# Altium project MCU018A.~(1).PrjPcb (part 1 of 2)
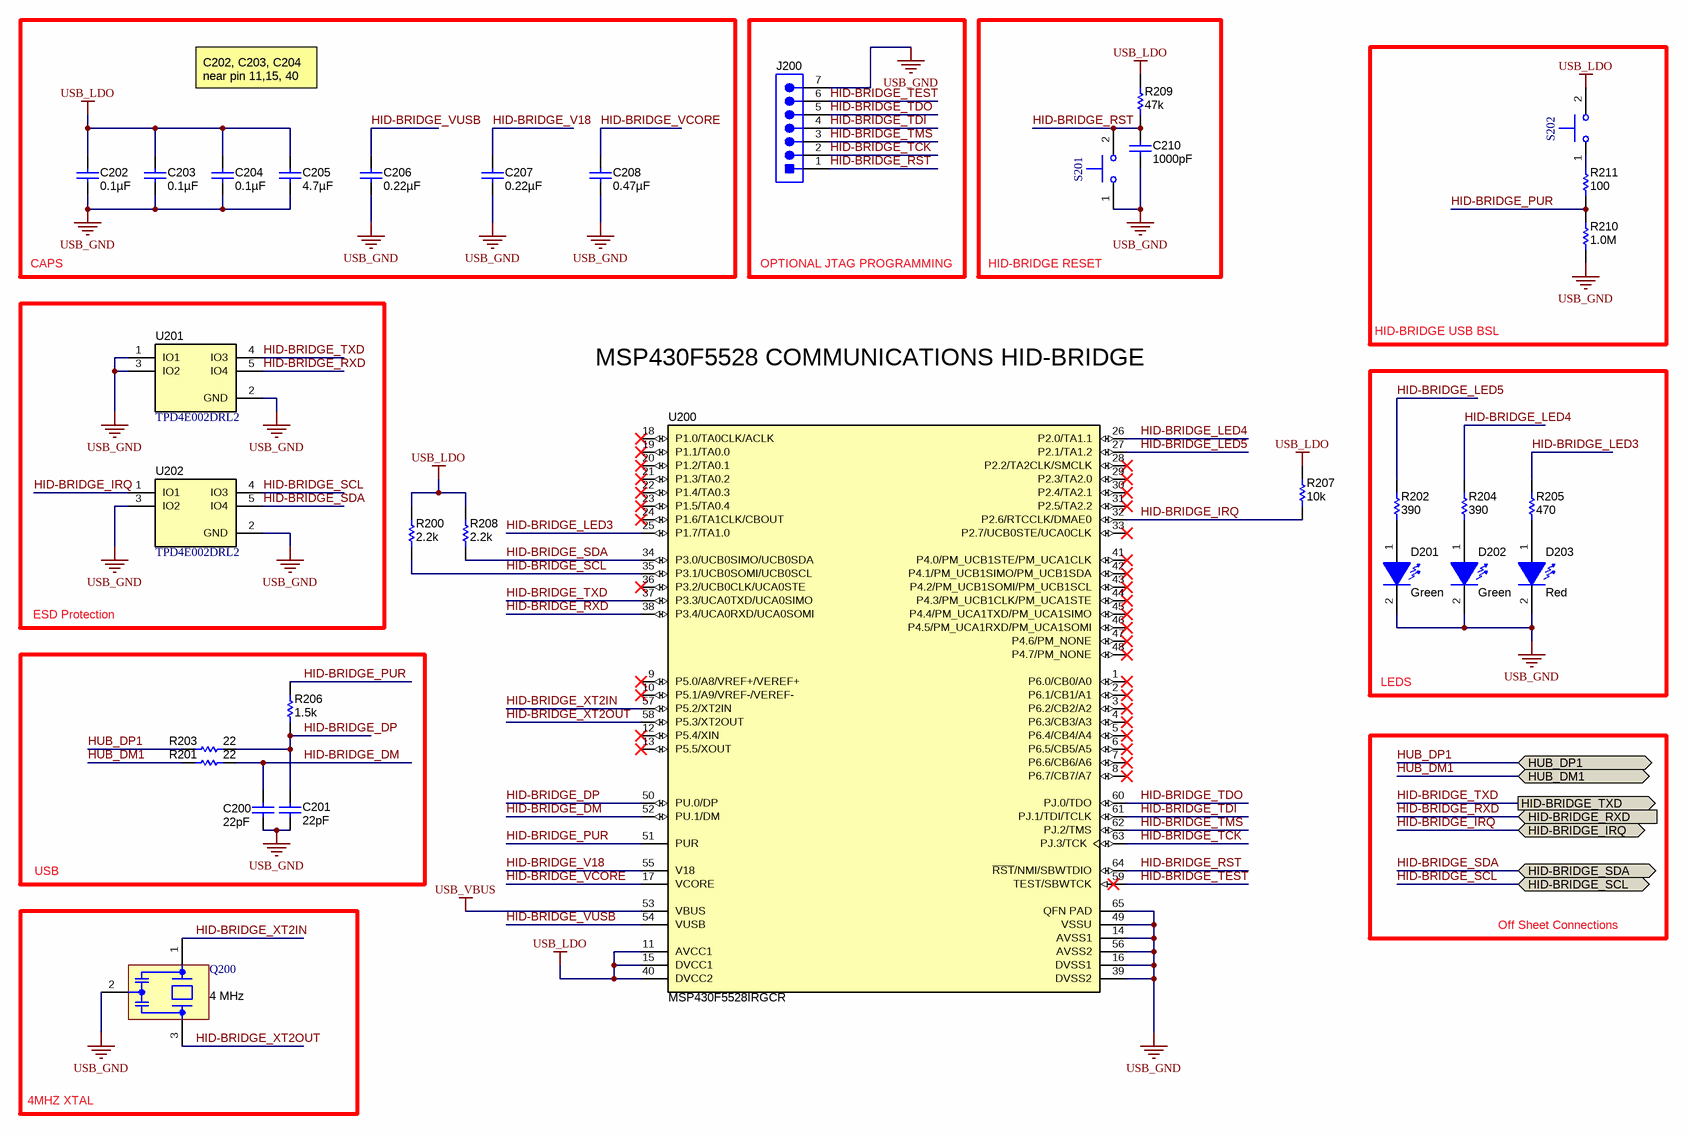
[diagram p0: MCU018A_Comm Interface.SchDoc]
TechSupport: http://www.ti.com/support; SCH_Rev: A; PRJ_Title: EVM430-FR6047; PRJ_Number: MCU018; PRJ_Engineer: Eddie LaCost; PRJ_Customer: Public Release; PCB_Rev: A; PCB_Layout: Eddie LaCost; Orderable: EVM430-FR6047; CopyrightYear: 2016
5 sheets, 255 parts. Net scope: hierarchical (ports join the sheet entries above them; power ports are global).
Board file: MCU018A.PcbDoc
Sheets:
  MCU018A_Comm Interface.SchDoc
  MCU018A_USB Hub and Pow.SchDoc
  MCU018A_Main.SchDoc
  MCU018A_ezFET_lite.SchDoc
  MCU018A_Hardware.SchDoc

## Sheet MCU018A_Comm Interface.SchDoc
size 431 x 279 mm; Date: Not shown in title block; ApprovedBy: Not shown in title block; CheckedBy: Not shown in title block; Author: Not shown in title block; CompanyName: Not shown in title block; Engineer: Not shown in title block; Organization: Not shown in title block; Address1: Not shown in title block; Address2: Not shown in title block; Address3: Not shown in title block; Address4: Not shown in title block; DocumentNumber: 5; Revision: Use project parameter SCH_Rev; SheetNumber: 5; SheetTotal: 6; PageSetup: Record=PageOptions¦CenterHorizontal=True¦CenterVertical=True¦PrintScale=0.62¦XCorrection=1.00¦YCorrection=1.00¦PrintKind=0¦BorderSize=5000000¦LeftOffset=0¦BottomOffset=0¦Orientation=2¦PaperLength=1000¦PaperWidth=1000¦Scale=100¦PaperSource=15¦PrintQuality=600¦MediaType=1¦DitherType=10¦PaperKind=Letter¦PrintScaleMode=1

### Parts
C200  ValueDisplayed: 22pF  [0402S]  (hidden comment: GRM1555C1H220JA01D)
C201  ValueDisplayed: 22pF  [0402S]  (hidden comment: GRM1555C1H220JA01D)
C202  ValueDisplayed: 0.1µF  [0402S]  (hidden comment: GRM155R71C104KA88D)
C203  ValueDisplayed: 0.1µF  [0402S]  (hidden comment: GRM155R71C104KA88D)
C204  ValueDisplayed: 0.1µF  [0402S]  (hidden comment: GRM155R71C104KA88D)
C205  ValueDisplayed: 4.7µF  [0603S]  (hidden comment: GRM188R61A475MAAJ)
C206  ValueDisplayed: 0.22µF  [0402S]  (hidden comment: GRM155R71C224KA12D)
C207  ValueDisplayed: 0.22µF  [0402S]  (hidden comment: GRM155R71C224KA12D)
C208  ValueDisplayed: 0.47µF  [0402S]  (hidden comment: GRM155R61C474KE01)
C210  ValueDisplayed: 1000pF  [0402S]  (hidden comment: GRM1555C1H102JA01D)
D201  value Green  [LTST-C191_Green]  (hidden comment: LTST-C191TGKT)
D202  value Green  [LTST-C191_Green]  (hidden comment: LTST-C191TGKT)
D203  value Red  [LED_LTST-C190_Red]  (hidden comment: LTST-C190CKT)
J200  PBC07SAAN  [Sullins_xxC07SAAN]  (value not drawn)
Q200  Frequency: 4 MHz  [Murata_CSTCR]  (hidden comment: CSTCR4M00G15L99-R0)
R200  ValueDisplayed: 2.2k  [0402S]  (hidden comment: CRCW04022K20JNED)
R201  ValueDisplayed: 22  [0402S]  (hidden comment: CRCW040222R0JNED)
R202  value 390  [0402S]  (hidden comment: CRCW0402390RJNED)
R203  ValueDisplayed: 22  [0402S]  (hidden comment: CRCW040222R0JNED)
R204  value 390  [0402S]  (hidden comment: CRCW0402390RJNED)
R205  ValueDisplayed: 470  [0402S]  (hidden comment: CRCW0402470RJNED)
R206  ValueDisplayed: 1.5k  [0402S]  (hidden comment: CRCW04021K50JNED)
R207  ValueDisplayed: 10k  [0402S]  (hidden comment: CRCW040210K0JNED)
R208  ValueDisplayed: 2.2k  [0402S]  (hidden comment: CRCW04022K20JNED)
R209  value 47k  [0402S]  (hidden comment: CRCW040247K0JNED)
R210  ValueDisplayed: 1.0M  [0402S]  (hidden comment: CRCW04021M00JNED)
R211  ValueDisplayed: 100  [0402S]  (hidden comment: CRCW0402100RJNED)
S201  B3U-1000P  [SW_B3U-1000P]  (value not drawn)
S202  B3U-1000P  [SW_B3U-1000P]  (value not drawn)
U200  MSP430F5528IRGCR  [RGC0064B]
U201  TPD4E002DRL2  [DRL0005A]
U202  TPD4E002DRL2  [DRL0005A]

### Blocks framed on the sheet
CAPS: C202-C208
OPTIONAL JTAG PROGRAMMING: J200
HID-BRIDGE RESET: C210 R209 S201
HID-BRIDGE USB BSL: R210 R211 S202
ESD Protection: U201 U202
LEDS: D201-D203 R202 R204 R205
USB: C200 C201 R201 R203 R206
4MHZ XTAL: Q200

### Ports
HID-BRIDGE_IRQ (bidir), HID-BRIDGE_RXD (in), HID-BRIDGE_SCL (bidir), HID-BRIDGE_SDA (bidir), HID-BRIDGE_TXD (out), HUB_DM1 (bidir), HUB_DP1 (bidir)

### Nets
USB_GND: C200.2 C201.2 C202.2 C203.2 C204.2 C205.2 C206.2 C207.2 C208.2 C210.2 D201.2(K) D202.2(K) D203.2(K) J200.7 Q200.2(GND) R210.1 S201.1 U200.14(AVSS1) U200.16(DVSS1) U200.39(DVSS2) U200.49(VSSU) U200.56(AVSS2) U200.65(QFN_PAD) U201.1(IO1) U201.2(GND) U201.3(IO2) U202.2(GND) U202.3(IO2)
USB_LDO: C202.1 C203.1 C204.1 C205.1 R200.2 R207.2 R208.2 R209.2 S202.2 U200.11(AVCC1) U200.15(DVCC1) U200.40(DVCC2)
USB_VBUS: U200.53(VBUS)
HID-BRIDGE_DM: C200.1 R201.2 U200.52(PU.1/DM)
HID-BRIDGE_DP: C201.1 R203.2 R206.1 U200.50(PU.0/DP)
HID-BRIDGE_IRQ: R207.1 U200.32(P2.6/RTCCLK/DMAE0) U202.1(IO1) ; port HID-BRIDGE_IRQ
HID-BRIDGE_LED3: R205.2 U200.25(P1.7/TA1.0)
HID-BRIDGE_LED4: R204.2 U200.26(P2.0/TA1.1)
HID-BRIDGE_LED5: R202.2 U200.27(P2.1/TA1.2)
HID-BRIDGE_PUR: R206.2 R210.2 R211.1 U200.51(PUR)
HID-BRIDGE_RST: C210.1 J200.1 R209.1 S201.2 U200.64(~{RST}/NMI/SBWTDIO)
HID-BRIDGE_RXD: U200.38(P3.4/UCA0RXD/UCA0SOMI) U201.5(IO4) ; port HID-BRIDGE_RXD
HID-BRIDGE_SCL: R200.1 U200.35(P3.1/UCB0SOMI/UCB0SCL) U202.4(IO3) ; port HID-BRIDGE_SCL
HID-BRIDGE_SDA: R208.1 U200.34(P3.0/UCB0SIMO/UCB0SDA) U202.5(IO4) ; port HID-BRIDGE_SDA
HID-BRIDGE_TCK: J200.2 U200.63(PJ.3/TCK)
HID-BRIDGE_TDI: J200.4 U200.61(PJ.1/TDI/TCLK)
HID-BRIDGE_TDO: J200.5 U200.60(PJ.0/TDO)
HID-BRIDGE_TEST: J200.6 U200.59(TEST/SBWTCK)
HID-BRIDGE_TMS: J200.3 U200.62(PJ.2/TMS)
HID-BRIDGE_TXD: U200.37(P3.3/UCA0TXD/UCA0SIMO) U201.4(IO3) ; port HID-BRIDGE_TXD
HID-BRIDGE_V18: C207.1 U200.55(V18)
HID-BRIDGE_VCORE: C208.1 U200.17(VCORE)
HID-BRIDGE_VUSB: C206.1 U200.54(VUSB)
HID-BRIDGE_XT2IN: Q200.1(In) U200.57(P5.2/XT2IN)
HID-BRIDGE_XT2OUT: Q200.3(Out) U200.58(P5.3/XT2OUT)
HUB_DM1: R201.1 ; port HUB_DM1
HUB_DP1: R203.1 ; port HUB_DP1
NetD201_1: D201.1(A) R202.1
NetD202_1: D202.1(A) R204.1
NetD203_1: D203.1(A) R205.1
NetR211_2: R211.2 S202.1

Not connected (* = marked no-connect by the designer): U200 1(P6.0/CB0/A0)* 2(P6.1/CB1/A1)* 3(P6.2/CB2/A2)* 4(P6.3/CB3/A3)* 5(P6.4/CB4/A4)* 6(P6.5/CB5/A5)* 7(P6.6/CB6/A6)* 8(P6.7/CB7/A7)* 9(P5.0/A8/VREF+/VEREF+)* 10(P5.1/A9/VREF-/VEREF-)* 12(P5.4/XIN)* 13(P5.5/XOUT)* 18(P1.0/TA0CLK/ACLK)* 19(P1.1/TA0.0)* 20(P1.2/TA0.1)* 21(P1.3/TA0.2)* 22(P1.4/TA0.3)* 23(P1.5/TA0.4)* 24(P1.6/TA1CLK/CBOUT)* 28(P2.2/TA2CLK/SMCLK)* 29(P2.3/TA2.0)* 30(P2.4/TA2.1)* 31(P2.5/TA2.2)* 33(P2.7/UCB0STE/UCA0CLK)* 36(P3.2/UCB0CLK/UCA0STE)* 41(P4.0/PM_UCB1STE/PM_UCA1CLK)* 42(P4.1/PM_UCB1SIMO/PM_UCB1SDA)* 43(P4.2/PM_UCB1SOMI/PM_UCB1SCL)* 44(P4.3/PM_UCB1CLK/PM_UCA1STE)* 45(P4.4/PM_UCA1TXD/PM_UCA1SIMO)* 46(P4.5/PM_UCA1RXD/PM_UCA1SOMI)* 47(P4.6/PM_NONE)* 48(P4.7/PM_NONE)*

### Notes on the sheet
- C202, C203, C204
  near pin 11,15, 40
- MSP430F5528 COMMUNICATIONS HID-BRIDGE
- Off Sheet Connections

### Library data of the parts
C200 C201 = GRM1555C1H220JA01D: CAP, CERM, 22 pF, 50 V, +/- 5%, C0G/NP0, 0402; Manufacturer: MuRata; Polarized: N; CompType: Capacitor; Value: 22pF; U/M: EA; Cap_F: 0.000000000022; Tolerance_%: 5; Value1: Unknown; VDC_V: 50; Value2: 50V; TaMin_C: -55; TaMax_C: 125; Cap_Case: 0402; AEC Category: Q200
C202-C204 = GRM155R71C104KA88D: CAP, CERM, 0.1 µF, 16 V, +/- 10%, X7R, 0402; Manufacturer: MuRata; Polarized: N; CompType: Capacitor; Value: 0.1uF; U/M: EA; Cap_F: 0.0000001; Tolerance_%: 10; Value1: Unknown; VDC_V: 16; Value2: 16V; TaMin_C: -55; TaMax_C: 125; Cap_Case: 0402
C205 = GRM188R61A475MAAJ: CAP, CERM, 4.7 µF, 10 V, +/- 20%, X5R, 0603; Manufacturer: MuRata; Polarized: N; CompType: Capacitor; Value: 4.7uF; U/M: EA; Cap_F: 0.0000047; Tolerance_%: 20; Value1: Unknown; VDC_V: 10; Value2: 10V; TaMin_C: -55; TaMax_C: 85; Cap_Case: 0603; AEC Category: Q200
C206 C207 = GRM155R71C224KA12D: CAP, CERM, 0.22 µF, 16 V, +/- 10%, X7R, 0402; Manufacturer: MuRata; Polarized: N; CompType: Capacitor; Value: 0.22uF; U/M: EA; Cap_F: 0.00000022; Tolerance_%: 10; Value1: Unknown; VDC_V: 16; Value2: 16V; TaMin_C: -55; TaMax_C: 125; Cap_Case: 0402
C208 = GRM155R61C474KE01: CAP, CERM, 0.47 µF, 16 V, +/- 10%, X5R, 0402; Manufacturer: MuRata; Polarized: N; CompType: Capacitor; Value: 0.47uF; U/M: EA; Cap_F: 0.00000047; Tolerance_%: 10; Value1: Unknown; VDC_V: 16; Value2: 16V; TaMin_C: -55; TaMax_C: 85; Cap_Case: 0402
C210 = GRM1555C1H102JA01D: CAP, CERM, 1000 pF, 50 V, +/- 5%, C0G/NP0, 0402; Manufacturer: MuRata; Polarized: N; CompType: Capacitor; Value: 1000pF; U/M: EA; Cap_F: 0.000000001; Tolerance_%: 5; Value1: Unknown; VDC_V: 50; Value2: 50V; TaMin_C: -55; TaMax_C: 125; Cap_Case: 0402
D201 D202 = LTST-C191TGKT: LED, Green, SMD; Manufacturer: Lite-On; Type: InGaN; Vf_V: 3.2; Value2: 3.2V; Io_A: 0.02; Value1: W; U/M: EA
D203 = LTST-C190CKT: LED, Red, SMD; Manufacturer: Lite-On; Vf_V: 2; Value2: 2V; Io_A: 0.02; Tjmax_C: 85; Power_TotalModule: 0.0625; Value1: 0.0625W; U/M: EA
J200 = PBC07SAAN: Header, 2.54 mm, 7x1, Gold, TH; Manufacturer: Sullins Connector Solutions; SymbolCreator: a0411947; Pitch_mm: 2.54; Gender: Male; Shrouded: N; Row_Count: 1; Current_A: 3; Voltage_V: 1800; Cert_UL: Y
Q200 = CSTCR4M00G15L99-R0: Resonator, 4MHz, 39pF SMD; Manufacturer: MuRata; SymbolCreator: a0799721; U/M: EA; TaMin_C: 0; TaMax_C: 70; Frequency Stability: ±0.08 %
R200 R208 = CRCW04022K20JNED: RES, 2.2 k, 5%, 0.063 W, 0402; Manufacturer: Vishay-Dale; CompType: Resistor; Value: 2.2k; Res_ohm: 2200; Value_Code: 2k20; Tolerance_%: 5; Power_W: 0.063; Value2: 0.063W; VDC_V: 50; TempCo: 200 ppm/C; EIA_Code: E24; U/M: EA; AEC Category: Q200
R201 R203 = CRCW040222R0JNED: RES, 22, 5%, 0.063 W, 0402; Manufacturer: Vishay-Dale; CompType: Resistor; Value: 22; Value_Code: 22R0; Tolerance_%: 5; Power_W: 0.063; Value2: 0.063W; VDC_V: 50; TempCo: 200 ppm/C; EIA_Code: E24; U/M: EA; AEC Category: Q200
R202 R204 = CRCW0402390RJNED: RES, 390 ohm, 5%, 0.063W, 0402; Manufacturer: Vishay-Dale; CompType: Resistor; Value_Code: 390R; Tolerance_%: 5; Power_W: 0.063; VDC_V: 50; TempCo: 200 ppm/C; EIA_Code: E24; U/M: EA
R205 = CRCW0402470RJNED: RES, 470, 5%, 0.063 W, 0402; Manufacturer: Vishay-Dale; CompType: Resistor; Value: 470; Value_Code: 470R; Tolerance_%: 5; Power_W: 0.063; Value2: 0.063W; VDC_V: 50; TempCo: 200 ppm/C; EIA_Code: E24; U/M: EA; AEC Category: Q200
R206 = CRCW04021K50JNED: RES, 1.5 k, 5%, 0.063 W, 0402; Manufacturer: Vishay-Dale; CompType: Resistor; Value: 1.5k; Res_ohm: 1500; Value_Code: 1k50; Tolerance_%: 5; Power_W: 0.063; Value2: 0.063W; VDC_V: 50; TempCo: 200 ppm/C; EIA_Code: E24; U/M: EA
R207 = CRCW040210K0JNED: RES, 10 k, 5%, 0.063 W, 0402; Manufacturer: Vishay-Dale; CompType: Resistor; Value: 10k; Res_ohm: 10000; Value_Code: 10k0; Tolerance_%: 5; Power_W: 0.063; Value2: 0.063W; VDC_V: 50; TempCo: 200 ppm/C; EIA_Code: E24; U/M: EA; AEC Category: Q200
R209 = CRCW040247K0JNED: RES, 47 k, 5%, 0.063 W, 0402; Manufacturer: Vishay-Dale; CompType: Resistor; Res_ohm: 47000; Value_Code: 47k0; Tolerance_%: 5; Power_W: 0.063; Value2: 0.063W; VDC_V: 50; TempCo: 200 ppm/C; EIA_Code: E24; U/M: EA
R210 = CRCW04021M00JNED: RES, 1.0 M, 5%, 0.063 W, 0402; Manufacturer: Vishay-Dale; CompType: Resistor; Value: 1.0Meg; Res_ohm: 1000000; Value_Code: 1M00; Tolerance_%: 5; Power_W: 0.063; Value2: 0.063W; VDC_V: 50; TempCo: 200 ppm/C; EIA_Code: E24; U/M: EA
R211 = CRCW0402100RJNED: RES, 100, 5%, 0.063 W, 0402; Manufacturer: Vishay-Dale; CompType: Resistor; Value: 100; Value_Code: 100R; Tolerance_%: 5; Power_W: 0.063; Value2: 0.063W; VDC_V: 50; TempCo: 200 ppm/C; EIA_Code: E24; U/M: EA
S201 S202 = B3U-1000P: SWITCH TACTILE SPST-NO 0.05A 12V; Manufacturer: Omron Electronic Components; SymbolCreator: a0412235; VDC_V: 12; SwitchFunction: Off-Mom; PositionCount: 1; CurrentRating_mA: 50
U200 = MSP430F5528IRGCR: Mixed Signal MicroController, RGC0064B; Manufacturer: Texas Instruments; Alternate PartNumber: MSP430F5528IRGCT; ADC: 12-bit SAR; ADC Channels: 16; Brown Out Reset: Yes; DMA: 3; Eco-Plan: Green (RoHS & no Sb/Br); Flash(KB): 128; Frequency(MHz): 25; GPIO: 47; Multiplier: 32x32; SRAM(B): 8192; SubFamily: 5 Series; Timers - 16-bit: 4; USB: 1; USCI_A (UART/LIN/IrDA/SPI): 2; SymbolCreator: Altium/a0412235; CompType: IC; U/M: EA
U201 U202 = TPD4E002DRL2: Low-Capacitance Array with + / - 15 kV ESD Protection, 4 Channels, -40 to +85 degC, 5-pin SOT (DRL), Green (RoHS & no Sb/Br); Manufacturer: Texas Instruments; Alternate PartNumber: Equivalent; Breakdown Voltage(Min)(V): 6; IEC 61000-4-2 Air-Gap(+/- kV): 15; IO Capacitance(Typ)(pF): 11; IO Leakage Current(nA): 100; SubFamily: ESD Solution

## Sheet MCU018A_USB Hub and Pow.SchDoc
size 431 x 279 mm; Date: Not shown in title block; ApprovedBy: Not shown in title block; CheckedBy: Not shown in title block; Author: Not shown in title block; CompanyName: Not shown in title block; Engineer: Not shown in title block; Organization: Not shown in title block; Address1: Not shown in title block; Address2: Not shown in title block; Address3: Not shown in title block; Address4: Not shown in title block; DocumentNumber: 3; Revision: Use project parameter SCH_Rev; SheetNumber: 3; SheetTotal: 6; PageSetup: Record=PageOptions¦CenterHorizontal=True¦CenterVertical=True¦PrintScale=1.00¦XCorrection=1.00¦YCorrection=1.00¦PrintKind=0¦BorderSize=5000000¦LeftOffset=0¦BottomOffset=0¦Orientation=2¦PaperLength=1000¦PaperWidth=1000¦Scale=100¦PaperSource=15¦PrintQuality=600¦MediaType=1¦DitherType=10¦PaperKind=Letter¦PrintScaleMode=1
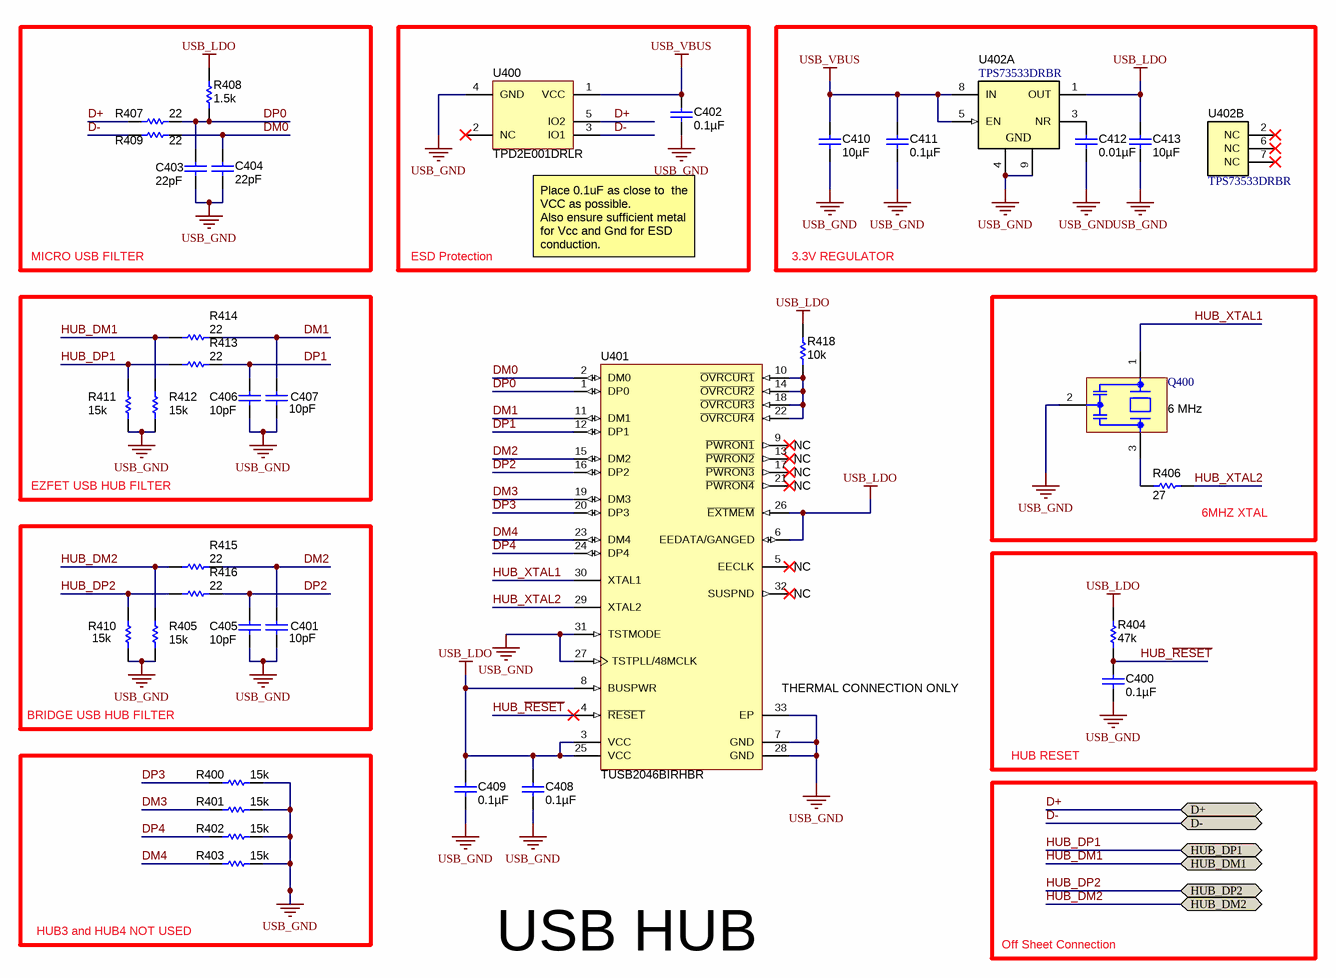
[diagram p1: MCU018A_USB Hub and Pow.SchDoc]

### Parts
C400  ValueDisplayed: 0.1µF  [0402S]  (hidden comment: GRM155R71C104KA88D)
C401  ValueDisplayed: 10pF  [0402S]  (hidden comment: GRM1555C1H100JA01D)
C402  ValueDisplayed: 0.1µF  [0402S]  (hidden comment: GRM155R71C104KA88D)
C403  ValueDisplayed: 22pF  [0402S]  (hidden comment: GRM1555C1H220JA01D)
C404  ValueDisplayed: 22pF  [0402S]  (hidden comment: GRM1555C1H220JA01D)
C405  ValueDisplayed: 10pF  [0402S]  (hidden comment: GRM1555C1H100JA01D)
C406  ValueDisplayed: 10pF  [0402S]  (hidden comment: GRM1555C1H100JA01D)
C407  ValueDisplayed: 10pF  [0402S]  (hidden comment: GRM1555C1H100JA01D)
C408  ValueDisplayed: 0.1µF  [0402S]  (hidden comment: GRM155R71C104KA88D)
C409  ValueDisplayed: 0.1µF  [0402S]  (hidden comment: GRM155R71C104KA88D)
C410  ValueDisplayed: 10µF  [0603S]  (hidden comment: GRM188R61A106ME69D)
C411  ValueDisplayed: 0.1µF  [0402S]  (hidden comment: GRM155R71C104KA88D)
C412  ValueDisplayed: 0.01µF  [0402S]  (hidden comment: GRM155R71C103KA01D)
C413  ValueDisplayed: 10µF  [0603S]  (hidden comment: GRM188R61A106ME69D)
Q400  Frequency: 6 MHz  [Murata_CSTCR]  (hidden comment: CSTCR6M00G53Z-R0)
R400  ValueDisplayed: 15k  [0402S]  (hidden comment: CRCW040215K0JNED)
R401  ValueDisplayed: 15k  [0402S]  (hidden comment: CRCW040215K0JNED)
R402  ValueDisplayed: 15k  [0402S]  (hidden comment: CRCW040215K0JNED)
R403  ValueDisplayed: 15k  [0402S]  (hidden comment: CRCW040215K0JNED)
R404  value 47k  [0402S]  (hidden comment: CRCW040247K0JNED)
R405  ValueDisplayed: 15k  [0402S]  (hidden comment: CRCW040215K0JNED)
R406  value 27  [0402S]  (hidden comment: CRCW040227R0JNED)
R407  value 22  [0402S]  (hidden comment: CRCW040222R0JNED)
R408  value 1.5k  [0402S]  (hidden comment: CRCW04021K50JNED)
R409  value 22  [0402S]  (hidden comment: CRCW040222R0JNED)
R410  ValueDisplayed: 15k  [0402S]  (hidden comment: CRCW040215K0JNED)
R411  ValueDisplayed: 15k  [0402S]  (hidden comment: CRCW040215K0JNED)
R412  ValueDisplayed: 15k  [0402S]  (hidden comment: CRCW040215K0JNED)
R413  value 22  [0402S]  (hidden comment: CRCW040222R0JNED)
R414  value 22  [0402S]  (hidden comment: CRCW040222R0JNED)
R415  value 22  [0402S]  (hidden comment: CRCW040222R0JNED)
R416  value 22  [0402S]  (hidden comment: CRCW040222R0JNED)
R418  ValueDisplayed: 10k  [0402S]  (hidden comment: CRCW040210K0JNED)
U400  TPD2E001DRLR  [DRL0005A]
U401  TUSB2046BIRHBR  [RHB0032E]
U402  TPS73533DRBR  [DRB0008A]  (parts A,B of 2)

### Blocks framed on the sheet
MICRO USB FILTER: C403 C404 R407-R409
ESD Protection: C402 U400
3.3V REGULATOR: C410-C413 U402
EZFET USB HUB FILTER: C406 C407 R411-R414
6MHZ XTAL: Q400 R406
BRIDGE USB HUB FILTER: C401 C405 R405 R410 R415 R416
HUB RESET: C400 R404
HUB3 and HUB4 NOT USED: R400-R403

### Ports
D+ (bidir), D- (bidir), HUB_DM1 (bidir), HUB_DM2 (bidir), HUB_DP1 (bidir), HUB_DP2 (bidir)

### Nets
USB_GND: C400.2 C401.2 C402.2 C403.2 C404.2 C405.2 C406.2 C407.2 C408.2 C409.2 C410.2 C411.2 C412.2 C413.2 Q400.2(GND) R400.1 R401.2 R402.2 R403.2 R405.1 R410.1 R411.1 R412.1 U400.4(GND) U401.7(GND) U401.27(TSTPLL/48MCLK) U401.28(GND) U401.31(TSTMODE) U401.33(EP) U402.4(GND) U402.9(GND)
USB_LDO: C408.1 C409.1 C413.1 R404.2 R408.2 R418.2 U401.3(VCC) U401.6(EEDATA/GANGED) U401.8(BUSPWR) U401.25(VCC) U401.26(~{EXTMEM}) U402.1(OUT)
USB_VBUS: C402.1 C410.1 C411.1 U400.1(VCC) U402.5(EN) U402.8(IN)
D+: R407.1 U400.5(IO2) ; port D+
D-: R409.1 U400.3(IO1) ; port D-
DM0: C404.1 R409.2 U401.2(DM0)
DM1: C407.1 R414.2 U401.11(DM1)
DM2: C401.1 R415.2 U401.15(DM2)
DM3: R401.1 U401.19(DM3)
DM4: R403.1 U401.23(DM4)
DP0: C403.1 R407.2 R408.1 U401.1(DP0)
DP1: C406.1 R413.2 U401.12(DP1)
DP2: C405.1 R416.2 U401.16(DP2)
DP3: R400.2 U401.20(DP3)
DP4: R402.1 U401.24(DP4)
HUB_DM1: R412.2 R414.1 ; port HUB_DM1
HUB_DM2: R405.2 R415.1 ; port HUB_DM2
HUB_DP1: R411.2 R413.1 ; port HUB_DP1
HUB_DP2: R410.2 R416.1 ; port HUB_DP2
HUB_~{RESET}: C400.1 R404.1 U401.4(~{RESET})
HUB_XTAL1: Q400.1(In) U401.30(XTAL1)
HUB_XTAL2: R406.2 U401.29(XTAL2)
NetC412_1: C412.1 U402.3(NR)
NetQ400_3: Q400.3(Out) R406.1
NetR418_1: R418.1 U401.10(~{OVRCUR1}) U401.14(~{OVRCUR2}) U401.18(~{OVRCUR3}) U401.22(~{OVRCUR4})

Not connected (* = marked no-connect by the designer): U400 2(NC)*; U401 5(EECLK)* 9(~{PWRON1})* 13(~{PWRON2})* 17(~{PWRON3})* 21(~{PWRON4})* 32(SUSPND)*; U402 2(NC)* 6(NC)* 7(NC)*

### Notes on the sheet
- Place 0.1uF as close to  the VCC as possible.
  Also ensure sufficient metal for Vcc and Gnd for ESD conduction.
- (near U401) NC
- (near U401) THERMAL CONNECTION ONLY
- USB HUB
- Off Sheet Connection

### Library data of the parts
C400 C402 C411 = GRM155R71C104KA88D: CAP, CERM, 0.1 µF, 16 V, +/- 10%, X7R, 0402; Manufacturer: MuRata; Polarized: N; CompType: Capacitor; Value: 0.1uF; U/M: EA; Cap_F: 0.0000001; Tolerance_%: 10; Value1: Unknown; VDC_V: 16; Value2: 16V; TaMin_C: -55; TaMax_C: 125; Cap_Case: 0402; AEC Category: Q200
C401 C405-C407 = GRM1555C1H100JA01D: CAP, CERM, 10 pF, 50 V, +/- 5%, C0G/NP0, 0402; Manufacturer: MuRata; Polarized: N; CompType: Capacitor; Value: 10pF; U/M: EA; Cap_F: 0.00000000001; Tolerance_%: 5; Value1: Unknown; VDC_V: 50; Value2: 50V; TaMin_C: -55; TaMax_C: 125; Cap_Case: 0402
C403 C404 = GRM1555C1H220JA01D: CAP, CERM, 22 pF, 50 V, +/- 5%, C0G/NP0, 0402; Manufacturer: MuRata; Polarized: N; CompType: Capacitor; Value: 22pF; U/M: EA; Cap_F: 0.000000000022; Tolerance_%: 5; Value1: Unknown; VDC_V: 50; Value2: 50V; TaMin_C: -55; TaMax_C: 125; Cap_Case: 0402
C408 C409 = GRM155R71C104KA88D: as C202 on sheet MCU018A_Comm Interface
C410 C413 = GRM188R61A106ME69D: CAP, CERM, 10 µF, 10 V, +/- 20%, X5R, 0603; Manufacturer: MuRata; Polarized: N; CompType: Capacitor; Value: 10uF; U/M: EA; Cap_F: 0.00001; Tolerance_%: 20; Value1: Unknown; VDC_V: 10; Value2: 10V; TaMin_C: -55; TaMax_C: 85; Cap_Case: 0603; AEC Category: Q200; SizeArea_mm2: 1.28; SizeAreaWB_mm2: 4.68; SizeX_mm: 1.6; SizeY_mm: 0.8; SizeZ_mm: 1
C412 = GRM155R71C103KA01D: CAP, CERM, 0.01 µF, 16 V, +/- 10%, X7R, 0402; Manufacturer: MuRata; Polarized: N; CompType: Capacitor; Value: 0.01uF; U/M: EA; Cap_F: 0.00000001; Tolerance_%: 10; Value1: Unknown; VDC_V: 16; Value2: 16V; TaMin_C: -55; TaMax_C: 125; Cap_Case: 0402; AEC Category: Q200; SizeArea_mm2: 0.5; SizeAreaWB_mm2: 3; SizeX_mm: 1; SizeZ_mm: 0.6
Q400 = CSTCR6M00G53Z-R0: Resonator, 6MHz, 15pF SMD; Manufacturer: MuRata; SymbolCreator: a0799721; U/M: EA; TaMin_C: -40; TaMax_C: 125; Frequency Stability: ±0.2 %
R400 R410 = CMP-0026842-3: RES, 15 k, 5%, 0.063 W, AEC-Q200 Grade 0, 0402; Manufacturer: Vishay-Dale; Power_W: 63mW; TempCo: 200 ppm/C; Value_Code: 15k0; Value: 15k; EIA_Code: E24; SizeX_mm: 1; SizeY_mm: 0.5; SizeZ_mm: 0.6; Value2: 0.063W; CompType: Resistor; AEC Qualified: Y; VDC_V: 50V; AEC Category: Q200; AEC Grade: 0
R401-R403 R405 R411 R412 = CRCW040215K0JNED: RES, 15 k, 5%, 0.063 W, 0402; Manufacturer: Vishay-Dale; CompType: Resistor; Value: 15k; Res_ohm: 15000; Value_Code: 15k0; Tolerance_%: 5; Power_W: 0.063; Value2: 0.063W; VDC_V: 50; TempCo: 200 ppm/C; EIA_Code: E24; U/M: EA
R404 = CRCW040247K0JNED: as R209 on sheet MCU018A_Comm Interface
R406 = CRCW040227R0JNED: RES, 27 ohm, 5%, 0.063W, 0402; Manufacturer: Vishay-Dale; CompType: Resistor; Value_Code: 27R0; Tolerance_%: 5; Power_W: 0.063; VDC_V: 50; TempCo: 200 ppm/C; EIA_Code: E24; U/M: EA
R407 R409 R413-R416 = CRCW040222R0JNED: RES, 22 ohm, 5%, 0.063W, 0402; Manufacturer: Vishay-Dale; CompType: Resistor; Value_Code: 22R0; Tolerance_%: 5; Power_W: 0.063; VDC_V: 50; TempCo: 200 ppm/C; EIA_Code: E24; U/M: EA
R408 = CRCW04021K50JNED: RES, 1.5 k, 5%, 0.063 W, 0402; Manufacturer: Vishay-Dale; CompType: Resistor; Res_ohm: 1500; Value_Code: 1k50; Tolerance_%: 5; Power_W: 0.063; Value2: 0.063W; VDC_V: 50; TempCo: 200 ppm/C; EIA_Code: E24; U/M: EA
R418 = CRCW040210K0JNED: as R207 on sheet MCU018A_Comm Interface
U400 = TPD2E001DRLR: Low-Capacitance + / - 15 kV ESD-Protection Array for High-Speed Data Interfaces, 2 Channels, -40 to +85 degC, 5-pin SOT (DRL), Green (RoHS & no Sb/Br); Manufacturer: Texas Instruments; Alternate Manufacturer: None; Alternate PartNumber: Equivalent; Breakdown Voltage(Min)(V): 11; IEC 61000-4-2 Air-Gap(+/- kV): 15; IEC 61000-4-2 Contact(+/- kV): 8; IO Capacitance(Typ)(pF): 1.5; IO Leakage Current(nA): 1; SubFamily: ESD Solution; USB High Speed: TRUE
U401 = TUSB2046BIRHBR: 4-Port Full-Speed USB Hub, 3.3V, -40 to 85 degC, 32-Pin QFN (RHB), Green (RoHS & no Sb/Br); Manufacturer: Texas Instruments; Alternate Manufacturer: None; Alternate PartNumber: Equivalent; SubFamily: USB Hub Controller; USB Speed: Full; USB Full Speed: True; Supply Voltage(s)(V): 3.3
U402 = TPS73533DRBR: Single Output High PSRR LDO, 500 mA, Fixed 3.3 V Output, 2.7 to 6.5 V Input, with Low IQ, 8-pin SON (DRB), -40 to 125 degC, Green (RoHS & no Sb/Br); Manufacturer: Texas Instruments; Alternate PartNumber: Equivalent; Accuracy(%): 2; Fixed Output Options(V): 3.3; Iout(Max)(A): 0.5; Iq(Typ)(mA): 0.04; SubFamily: Single Channel LDO; Vdo(Typ)(mV): 280; Vin(Max)(V): 6.5; Vin(Min)(V): 2.7

## Sheet MCU018A_Main.SchDoc
size 558 x 431 mm; Date: Not shown in title block; ApprovedBy: Not shown in title block; CheckedBy: Not shown in title block; Author: Not shown in title block; CompanyName: Not shown in title block; Engineer: Eddie LaCost; Organization: Not shown in title block; Address1: Not shown in title block; Address2: Not shown in title block; Address3: Not shown in title block; Address4: Not shown in title block; DocumentNumber: 2; Revision: Use project parameter SCH_Rev; SheetNumber: 2; SheetTotal: 6; PageSetup: Record=PageOptions¦CenterHorizontal=True¦CenterVertical=True¦PrintScale=1.00¦XCorrection=1.00¦YCorrection=1.00¦PrintKind=0¦BorderSize=5000000¦LeftOffset=0¦BottomOffset=0¦Orientation=2¦PaperLength=1000¦PaperWidth=1000¦Scale=100¦PaperSource=15¦PrintQuality=600¦MediaType=1¦DitherType=10¦PaperKind=Letter¦PrintScaleMode=1
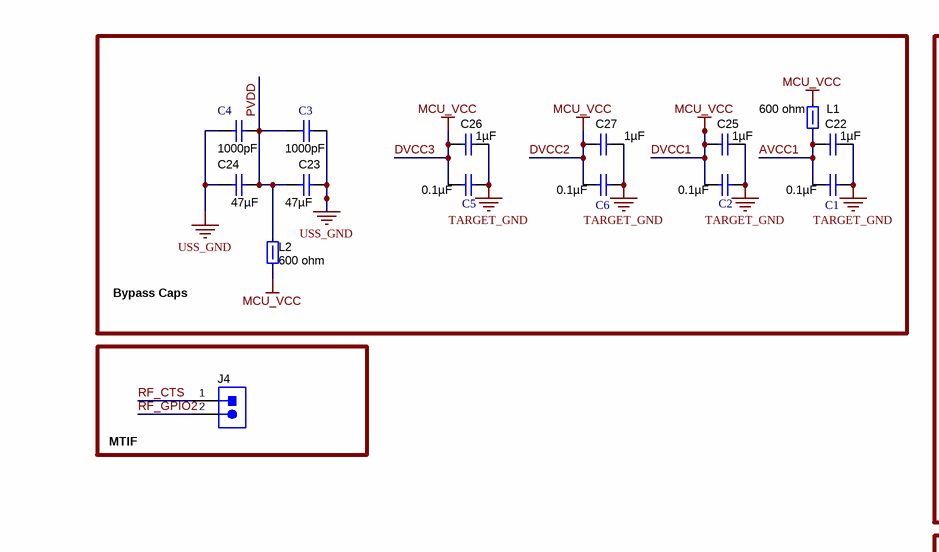
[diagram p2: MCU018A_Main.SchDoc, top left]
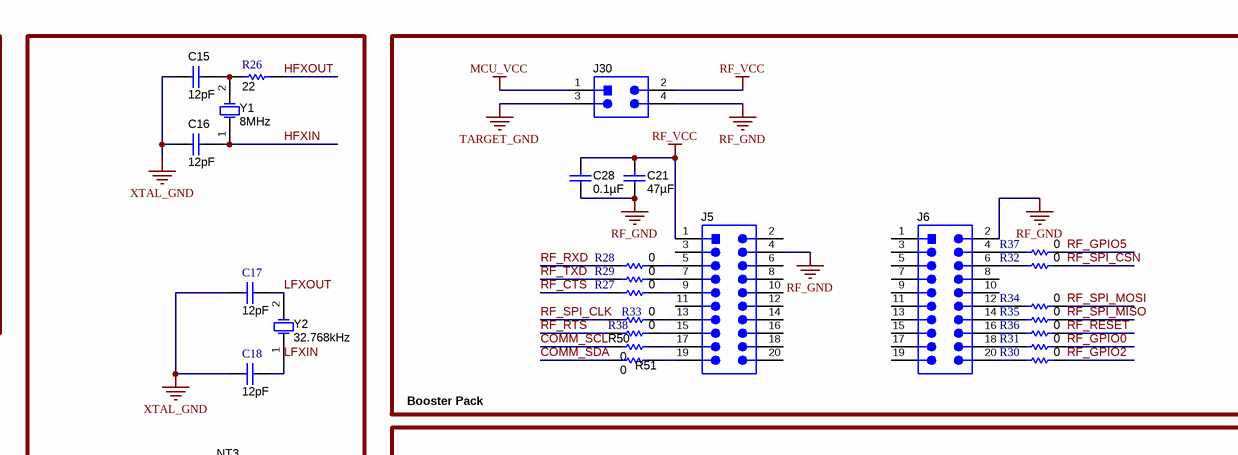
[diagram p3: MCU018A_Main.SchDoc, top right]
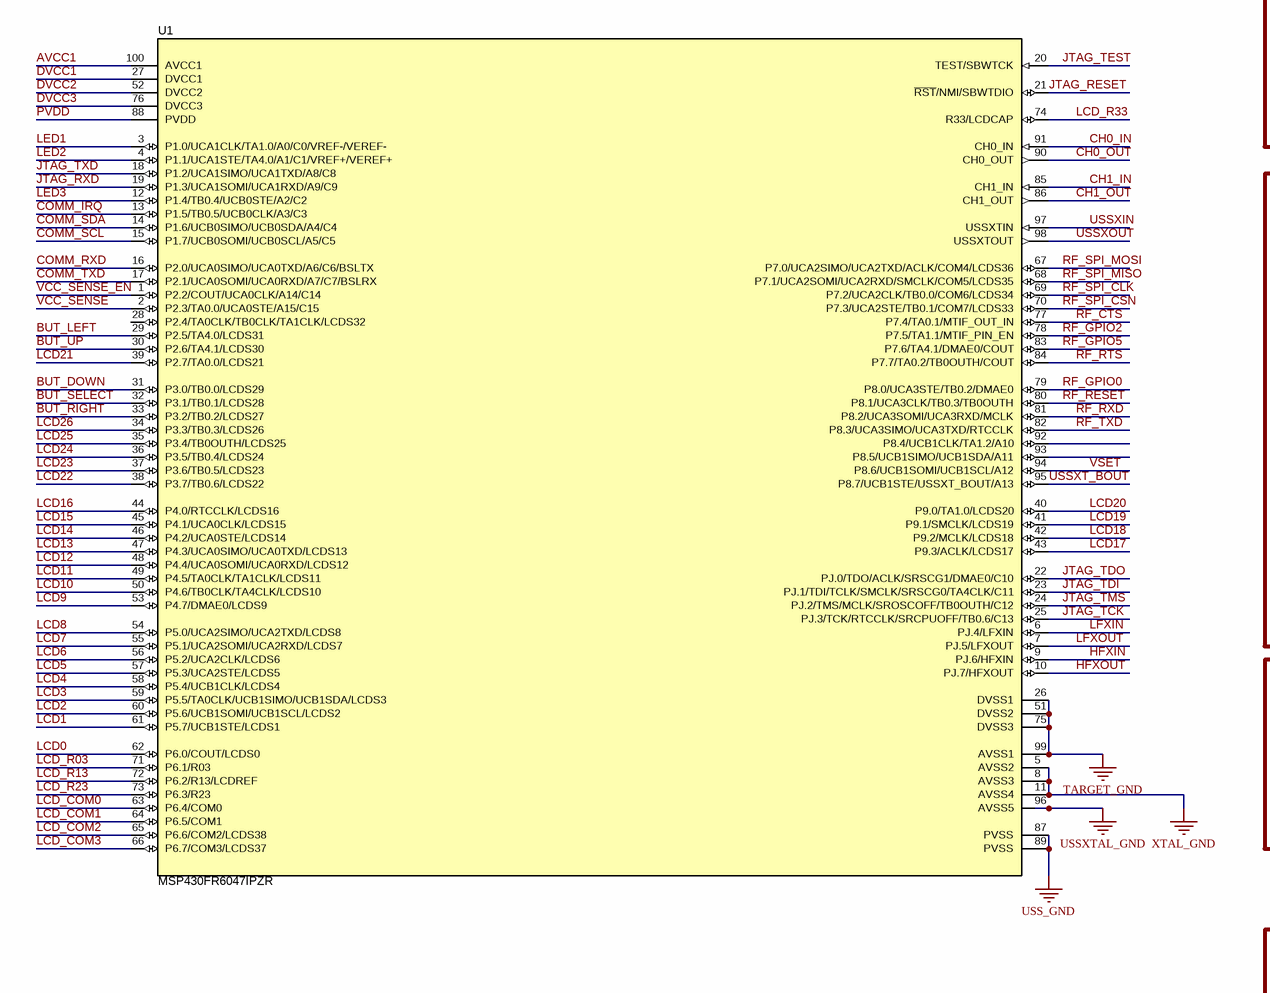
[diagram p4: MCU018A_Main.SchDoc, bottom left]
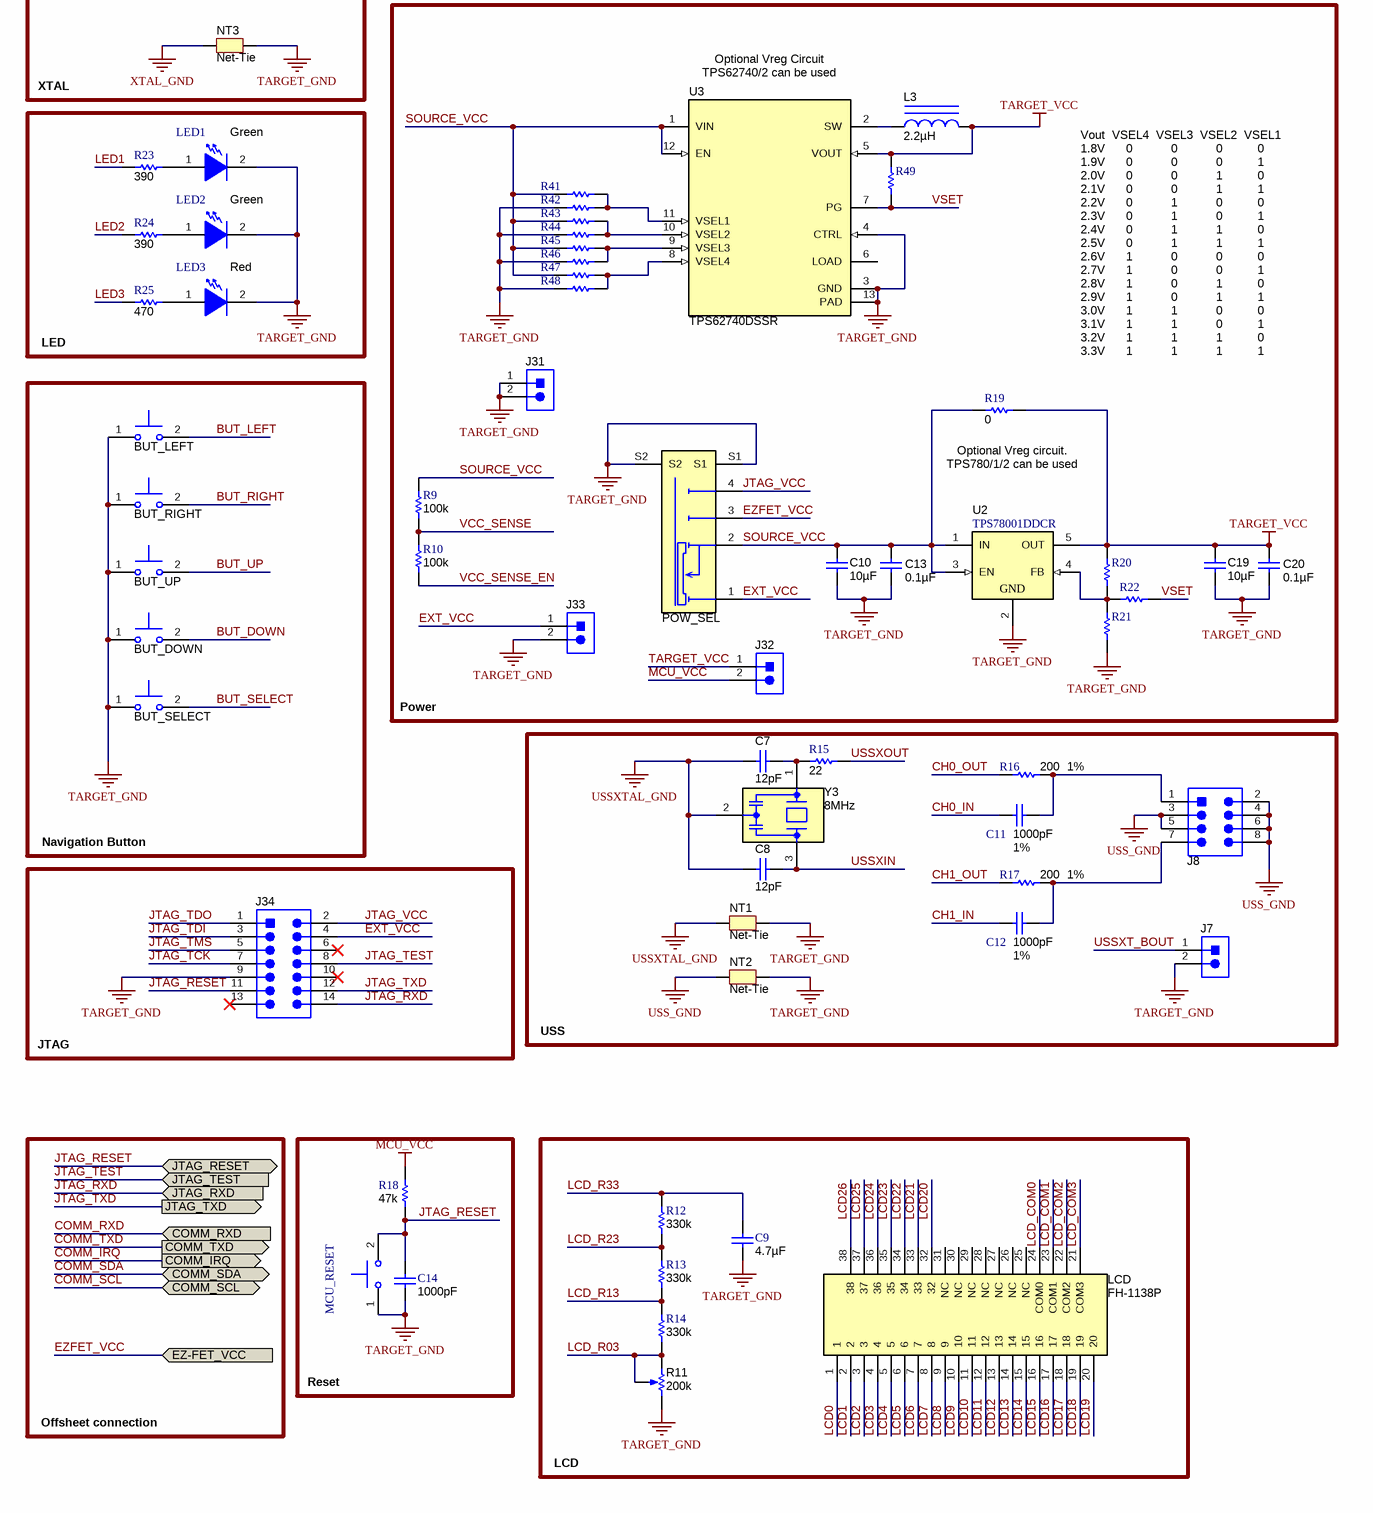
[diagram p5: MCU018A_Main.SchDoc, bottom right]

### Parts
BUT_DOWN  TL1015AF160QG  [SW_TL1015AF160QG]  (value not drawn)
BUT_LEFT  TL1015AF160QG  [SW_TL1015AF160QG]  (value not drawn)
BUT_RIGHT  TL1015AF160QG  [SW_TL1015AF160QG]  (value not drawn)
BUT_SELECT  TL1015AF160QG  [SW_TL1015AF160QG]  (value not drawn)
BUT_UP  TL1015AF160QG  [SW_TL1015AF160QG]  (value not drawn)
C1  ValueDisplayed: 0.1µF  [0402S]  (hidden comment: GRM155R71C104KA88D)
C2  ValueDisplayed: 0.1µF  [0402S]  (hidden comment: GRM155R71C104KA88D)
C3  ValueDisplayed: 1000pF  [0402S]  (hidden comment: GRM1555C1H102JA01D)
C4  ValueDisplayed: 1000pF  [0402S]  (hidden comment: GRM1555C1H102JA01D)
C5  ValueDisplayed: 0.1µF  [0402S]  (hidden comment: GRM155R71C104KA88D)
C6  ValueDisplayed: 0.1µF  [0402S]  (hidden comment: GRM155R71C104KA88D)
C7  ValueDisplayed: 12pF  [0402]  (hidden comment: GRM1555C1H120JA01D)
C8  ValueDisplayed: 12pF  [0402]  (hidden comment: GRM1555C1H120JA01D)
C9  ValueDisplayed: 4.7µF  [0805_HV]  (hidden comment: GRM21BR71C475KA73L)
C10  ValueDisplayed: 10µF  [0603S]  (hidden comment: GRM188R61A106ME69D)
C11  ValueDisplayed: 1000pF  Tolerance_%: 1%  [0603S]  (hidden comment: GRM1885C1H102FA01J)
C12  ValueDisplayed: 1000pF  Tolerance_%: 1%  [0603S]  (hidden comment: GRM1885C1H102FA01J)
C13  ValueDisplayed: 0.1µF  [0402S]  (hidden comment: GRM155R71C104KA88D)
C14  ValueDisplayed: 1000pF  [0402S]  (hidden comment: GRM1555C1H102JA01D)
C15  ValueDisplayed: 12pF  [0402]  (hidden comment: GRM1555C1H120JA01D)
C16  ValueDisplayed: 12pF  [0402]  (hidden comment: GRM1555C1H120JA01D)
C17  ValueDisplayed: 12pF  [0402S]  (hidden comment: GRM1555C1H120JA01D)
C18  ValueDisplayed: 12pF  [0402S]  (hidden comment: GRM1555C1H120JA01D)
C19  ValueDisplayed: 10µF  [0603S]  (hidden comment: GRM188R61A106ME69D)
C20  ValueDisplayed: 0.1µF  [0402S]  (hidden comment: GRM155R71C104KA88D)
C21  ValueDisplayed: 47µF  [0805_HV]  (hidden comment: GRM21BR60J476ME15L)
C22  ValueDisplayed: 1µF  [0603S]  (hidden comment: GRM188R71A105KA61D)
C23  ValueDisplayed: 47µF  [0805L]  (hidden comment: GRM21BR60J476ME15L)
C24  ValueDisplayed: 47µF  [0805L]  (hidden comment: GRM21BR60J476ME15L)
C25  ValueDisplayed: 1µF  [0603S]  (hidden comment: GRM188R71A105KA61D)
C26  ValueDisplayed: 1µF  [0603S]  (hidden comment: GRM188R71A105KA61D)
C27  ValueDisplayed: 1µF  [0603S]  (hidden comment: GRM188R71A105KA61D)
C28  ValueDisplayed: 0.1µF  [0402]  (hidden comment: GRM155R71C104KA88D)
J4  HMTSW-102-07-G-S-240  [SAMTEC_HMTSW-102-07-G-S-240]  (value not drawn)
J5  TSW-110-07-G-D  [TSW-110-07-G-D]  (value not drawn)
J6  TSW-110-07-G-D  [TSW-110-07-G-D]  (value not drawn)
J7  HMTSW-102-07-G-S-240  [SAMTEC_HMTSW-102-07-G-S-240]  (value not drawn)
J8  TSW-104-07-G-D  [TSW-104-07-G-D]  (value not drawn)
J30  TSW-102-07-G-D  [TSW-102-07-G-D]  (value not drawn)
J31  TSW-102-07-G-S  [TSW-102-07-G-S]  (value not drawn)
J32  TSW-102-07-G-S  [TSW-102-07-G-S]  (value not drawn)
J33  TSW-102-07-G-S  [TSW-102-07-G-S]  (value not drawn)
J34  SBH11-PBPC-D07-ST-BK  [CONN_SBH11-PBPC-D07-ST-BK]  (value not drawn)
L1  value 600 ohm  [0805L]  (hidden comment: MPZ2012S601A)
L2  value 600 ohm  [0805L]  (hidden comment: MPZ2012S601A)
L3  ValueDisplayed: 2.2µH  [VLF302515MT]  (hidden comment: VLF302515MT-2R2M)
LCD  FH-1138P  [ADKOM_FH-1138P]
LED1  value Green  [LTST-C191_Green]  (hidden comment: LTST-C191TGKT)
LED2  value Green  [LTST-C191_Green]  (hidden comment: LTST-C191TGKT)
LED3  value Red  [LED_LTST-C190_Red]  (hidden comment: LTST-C190CKT)
MCU_RESET  B3U-1000P  [SW_B3U-1000P]  (value not drawn)
NT1  Net-Tie  [Net-Tie_50milWide_30milLong]  (net tie, no BOM)
NT2  Net-Tie  [Net-Tie_50milWide_30milLong]  (net tie, no BOM)
NT3  Net-Tie  [Net-Tie_50milWide_30milLong]  (net tie, no BOM)
POW_SEL  SS-13D16-VG 4 PA  [SW_SS-13D16-VG]  (value not drawn)
R9  ValueDisplayed: 100k  [0402S]  (hidden comment: CRCW0402100KJNED)
R10  ValueDisplayed: 100k  [0402S]  (hidden comment: CRCW0402100KJNED)
R11  value 200k  [TRIM_3224W]  (hidden comment: 3224W-1-204E)
R12  ValueDisplayed: 330k  [0402S]  (hidden comment: CRCW0402330KJNED)
R13  ValueDisplayed: 330k  [0402S]  (hidden comment: CRCW0402330KJNED)
R14  ValueDisplayed: 330k  [0402S]  (hidden comment: CRCW0402330KJNED)
R15  ValueDisplayed: 22  [0402S]  (hidden comment: CRCW040222R0JNED)
R16  ValueDisplayed: 200  Value1: 1%  [0402S]  (hidden comment: CRCW0402200RFKED)
R17  ValueDisplayed: 200  Value1: 1%  [0402S]  (hidden comment: CRCW0402200RFKED)
R18  ValueDisplayed: 47k  [0402S]  (hidden comment: CRCW040247K0JNED)
R19  ValueDisplayed: 0  [0805_HV]  (hidden comment: CRCW08050000Z0EA)
R20  Used in BOM report  [0402S]  (value not drawn)
R21  Used in BOM report  [0402S]  (value not drawn)
R22  Used in BOM report  [0402S]  (value not drawn)
R23  ValueDisplayed: 390  [0402S]  (hidden comment: CRCW0402390RJNED)
R24  ValueDisplayed: 390  [0402S]  (hidden comment: CRCW0402390RJNED)
R25  ValueDisplayed: 470  [0402S]  (hidden comment: CRCW0402470RJNED)
R26  ValueDisplayed: 22  [0402S]  (hidden comment: CRCW040222R0JNED)
R27  ValueDisplayed: 0  [0402S]  (hidden comment: CRCW04020000Z0ED)
R28  ValueDisplayed: 0  [0402S]  (hidden comment: CRCW04020000Z0ED)
R29  ValueDisplayed: 0  [0402S]  (hidden comment: CRCW04020000Z0ED)
R30  ValueDisplayed: 0  [0402S]  (hidden comment: CRCW04020000Z0ED)
R31  ValueDisplayed: 0  [0402S]  (hidden comment: CRCW04020000Z0ED)
R32  ValueDisplayed: 0  [0402S]  (hidden comment: CRCW04020000Z0ED)
R33  ValueDisplayed: 0  [0402S]  (hidden comment: CRCW04020000Z0ED)
R34  ValueDisplayed: 0  [0402S]  (hidden comment: CRCW04020000Z0ED)
R35  ValueDisplayed: 0  [0402S]  (hidden comment: CRCW04020000Z0ED)
R36  ValueDisplayed: 0  [0402S]  (hidden comment: CRCW04020000Z0ED)
R37  ValueDisplayed: 0  [0402S]  (hidden comment: CRCW04020000Z0ED)
R38  ValueDisplayed: 0  [0402S]  (hidden comment: CRCW04020000Z0ED)
R41  Used in BOM report  [0402S]  (value not drawn)
R42  Used in BOM report  [0402S]  (value not drawn)
R43  Used in BOM report  [0402S]  (value not drawn)
R44  Used in BOM report  [0402S]  (value not drawn)
R45  Used in BOM report  [0402S]  (value not drawn)
R46  Used in BOM report  [0402S]  (value not drawn)
R47  Used in BOM report  [0402S]  (value not drawn)
R48  Used in BOM report  [0402S]  (value not drawn)
R49  Used in BOM report  [0402S]  (value not drawn)
R50  ValueDisplayed: 0  [0402S]  (hidden comment: CRCW04020000Z0ED)
R51  ValueDisplayed: 0  [0402S]  (hidden comment: CRCW04020000Z0ED)
U1  MSP430FR6047IPZR  [PZ0100A_N]
U2  TPS78001DDCR  [DDC0005A_N]
U3  TPS62740DSSR  [DSS0012A]
Y1  Frequency: 8MHz  [Abracon_ABM3]  (hidden comment: ABM3-8.000MHZ-D2Y-T)
Y2  Frequency: 32.768kHz  [XTAL_ABS07]  (hidden comment: ABS07-32.768KHZ-9-T)
Y3  Frequency: 8MHz  [Abracon_AWSCR-CV]  (hidden comment: AWSCR-8.00CV-T)

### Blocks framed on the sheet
Bypass Caps: C1-C6 C22-C27 L1 L2
XTAL: C15-C18 NT3 R26 Y1 Y2
Booster Pack: C21 C28 J5 J6 J30 R27-R38 R50 R51
MTIF: J4
LED: LED1-LED3 R23-R25
Navigation Button: BUT_DOWN BUT_LEFT BUT_RIGHT BUT_SELECT BUT_UP
USS: C7 C8 C11 C12 J7 J8 NT1 NT2 R15-R17 Y3
JTAG: J34
Reset: C14 MCU_RESET R18
LCD: C9 LCD R11-R14

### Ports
COMM_IRQ (out), COMM_RXD (in), COMM_SCL (bidir), COMM_SDA (bidir), COMM_TXD (out), EZ-FET_VCC, JTAG_RESET (bidir), JTAG_RXD (in), JTAG_TEST (in), JTAG_TXD (out)

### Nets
DVCC1: C2.2 C5.1 C6.1 C25.1 C26.1 C27.2 J30.1 J32.2 L1.2 L2.2 R18.2 U1.27(DVCC1) U1.52(DVCC2) U1.76(DVCC3)  [also labelled DVCC2, DVCC3, MCU_VCC]
RF_GND: C21.2 C28.2 J5.4 J6.2 J30.4
RF_VCC: C21.1 C28.1 J5.1 J30.2
TARGET_GND: BUT_DOWN.1 BUT_LEFT.1 BUT_RIGHT.1 BUT_SELECT.1 BUT_UP.1 C1.2 C2.1 C5.2 C6.2 C9.2 C10.2 C13.2 C14.2 C19.2 C20.2 C22.2 C25.2 C26.2 C27.1 J7.2 J30.3 J31.1 J31.2 J33.2 J34.9 LED1.2(K) LED2.2(K) LED3.2(K) MCU_RESET.1 NT1.2 NT2.2 NT3.2 POW_SEL.S1 POW_SEL.S2 R11.3(CW) R21.1 R42.2 R44.2 R46.2 R48.2 U1.26(DVSS1) U1.51(DVSS2) U1.75(DVSS3) U1.99(AVSS1) U2.2(GND) U3.3(GND) U3.4(CTRL) U3.13(PAD)
TARGET_VCC: C19.1 C20.1 J32.1 L3.2 R19.1 R20.2 R49.1 U2.5(OUT) U3.5(VOUT)
USS_GND: C3.1 C4.2 C23.2 C24.1 J8.2 J8.3 J8.4 J8.5 J8.6 J8.8 NT2.1 U1.87(PVSS) U1.89(PVSS)
USSXTAL_GND: C7.2 C8.2 NT1.1 U1.96(AVSS5) Y3.2(GND)
XTAL_GND: C15.2 C16.2 C17.1 C18.2 NT3.1 U1.5(AVSS2) U1.8(AVSS3) U1.11(AVSS4)
AVCC1: C1.1 C22.1 L1.1 U1.100(AVCC1)
BUT_DOWN: BUT_DOWN.2 U1.31(P3.0/TB0.0/LCDS29)
BUT_LEFT: BUT_LEFT.2 U1.29(P2.5/TA4.0/LCDS31)
BUT_RIGHT: BUT_RIGHT.2 U1.33(P3.2/TB0.2/LCDS27)
BUT_SELECT: BUT_SELECT.2 U1.32(P3.1/TB0.1/LCDS28)
BUT_UP: BUT_UP.2 U1.30(P2.6/TA4.1/LCDS30)
CH0_IN: C11.1 U1.91(CH0_IN)
CH0_OUT: R16.2 U1.90(CH0_OUT)
CH1_IN: C12.1 U1.85(CH1_IN)
CH1_OUT: R17.2 U1.86(CH1_OUT)
COMM_IRQ: U1.13(P1.5/TB0.5/UCB0CLK/A3/C3) ; port COMM_IRQ
COMM_RXD: U1.16(P2.0/UCA0SIMO/UCA0TXD/A6/C6/BSLTX) ; port COMM_RXD
COMM_SCL: R50.1 U1.15(P1.7/UCB0SOMI/UCB0SCL/A5/C5) ; port COMM_SCL
COMM_SDA: R51.1 U1.14(P1.6/UCB0SIMO/UCB0SDA/A4/C4) ; port COMM_SDA
COMM_TXD: U1.17(P2.1/UCA0SOMI/UCA0RXD/A7/C7/BSLRX) ; port COMM_TXD
EXT_VCC: J33.1 J34.4 POW_SEL.1
EZFET_VCC: POW_SEL.3 ; port EZ-FET_VCC
HFXIN: C16.1 U1.9(PJ.6/HFXIN) Y1.1(OSC1)
HFXOUT: R26.2 U1.10(PJ.7/HFXOUT)
JTAG_RESET: C14.1 J34.11 MCU_RESET.2 R18.1 U1.21(~{RST}/NMI/SBWTDIO) ; port JTAG_RESET
JTAG_RXD: J34.14 U1.19(P1.3/UCA1SOMI/UCA1RXD/A9/C9) ; port JTAG_RXD
JTAG_TCK: J34.7 U1.25(PJ.3/TCK/RTCCLK/SRCPUOFF/TB0.6/C13)
JTAG_TDI: J34.3 U1.23(PJ.1/TDI/TCLK/SMCLK/SRSCG0/TA4CLK/C11)
JTAG_TDO: J34.1 U1.22(PJ.0/TDO/ACLK/SRSCG1/DMAE0/C10)
JTAG_TEST: J34.8 U1.20(TEST/SBWTCK) ; port JTAG_TEST
JTAG_TMS: J34.5 U1.24(PJ.2/TMS/MCLK/SROSCOFF/TB0OUTH/C12)
JTAG_TXD: J34.12 U1.18(P1.2/UCA1SIMO/UCA1TXD/A8/C8) ; port JTAG_TXD
JTAG_VCC: J34.2 POW_SEL.4
LCD0: LCD.1 U1.62(P6.0/COUT/LCDS0)
LCD1: LCD.2 U1.61(P5.7/UCB1STE/LCDS1)
LCD2: LCD.3 U1.60(P5.6/UCB1SOMI/UCB1SCL/LCDS2)
LCD3: LCD.4 U1.59(P5.5/TA0CLK/UCB1SIMO/UCB1SDA/LCDS3)
LCD4: LCD.5 U1.58(P5.4/UCB1CLK/LCDS4)
LCD5: LCD.6 U1.57(P5.3/UCA2STE/LCDS5)
LCD6: LCD.7 U1.56(P5.2/UCA2CLK/LCDS6)
LCD7: LCD.8 U1.55(P5.1/UCA2SOMI/UCA2RXD/LCDS7)
LCD8: LCD.9 U1.54(P5.0/UCA2SIMO/UCA2TXD/LCDS8)
LCD9: LCD.10 U1.53(P4.7/DMAE0/LCDS9)
LCD10: LCD.11 U1.50(P4.6/TB0CLK/TA4CLK/LCDS10)
LCD11: LCD.12 U1.49(P4.5/TA0CLK/TA1CLK/LCDS11)
LCD12: LCD.13 U1.48(P4.4/UCA0SOMI/UCA0RXD/LCDS12)
LCD13: LCD.14 U1.47(P4.3/UCA0SIMO/UCA0TXD/LCDS13)
LCD14: LCD.15 U1.46(P4.2/UCA0STE/LCDS14)
LCD15: LCD.16 U1.45(P4.1/UCA0CLK/LCDS15)
LCD16: LCD.17 U1.44(P4.0/RTCCLK/LCDS16)
LCD17: LCD.18 U1.43(P9.3/ACLK/LCDS17)
LCD18: LCD.19 U1.42(P9.2/MCLK/LCDS18)
LCD19: LCD.20 U1.41(P9.1/SMCLK/LCDS19)
LCD20: LCD.32 U1.40(P9.0/TA1.0/LCDS20)
LCD21: LCD.33 U1.39(P2.7/TA0.0/LCDS21)
LCD22: LCD.34 U1.38(P3.7/TB0.6/LCDS22)
LCD23: LCD.35 U1.37(P3.6/TB0.5/LCDS23)
LCD24: LCD.36 U1.36(P3.5/TB0.4/LCDS24)
LCD25: LCD.37 U1.35(P3.4/TB0OUTH/LCDS25)
LCD26: LCD.38 U1.34(P3.3/TB0.3/LCDS26)
LCD_COM0: LCD.24(COM0) U1.63(P6.4/COM0)
LCD_COM1: LCD.23(COM1) U1.64(P6.5/COM1)
LCD_COM2: LCD.22(COM2) U1.65(P6.6/COM2/LCDS38)
LCD_COM3: LCD.21(COM3) U1.66(P6.7/COM3/LCDS37)
LCD_R03: R11.1(CCW) R11.2(WIPER) R14.2 U1.71(P6.1/R03)
LCD_R13: R13.1 R14.1 U1.72(P6.2/R13/LCDREF)
LCD_R23: R12.1 R13.2 U1.73(P6.3/R23)
LCD_R33: C9.1 R12.2 U1.74(R33/LCDCAP)
LED1: R23.1 U1.3(P1.0/UCA1CLK/TA1.0/A0/C0/VREF-/VEREF-)
LED2: R24.1 U1.4(P1.1/UCA1STE/TA4.0/A1/C1/VREF+/VEREF+)
LED3: R25.1 U1.12(P1.4/TB0.4/UCB0STE/A2/C2)
LFXIN: C18.1 U1.6(PJ.4/LFXIN) Y2.1(OSC1)
LFXOUT: C17.2 U1.7(PJ.5/LFXOUT) Y2.2(OSC2)
PVDD: C3.2 C4.1 C23.1 C24.2 L2.1 U1.88(PVDD)
RF_CTS: J4.1 R27.2 U1.77(P7.4/TA0.1/MTIF_OUT_IN)
RF_GPIO0: R31.2 U1.79(P8.0/UCA3STE/TB0.2/DMAE0)
RF_GPIO2: J4.2 R30.2 U1.78(P7.5/TA1.1/MTIF_PIN_EN)
RF_GPIO5: R37.1 U1.83(P7.6/TA4.1/DMAE0/COUT)
RF_RESET: R36.1 U1.80(P8.1/UCA3CLK/TB0.3/TB0OUTH)
RF_RTS: R38.1 U1.84(P7.7/TA0.2/TB0OUTH/COUT)
RF_RXD: R28.2 U1.81(P8.2/UCA3SOMI/UCA3RXD/MCLK)
RF_SPI_CLK: R33.1 U1.69(P7.2/UCA2CLK/TB0.0/COM6/LCDS34)
RF_SPI_CSN: R32.2 U1.70(P7.3/UCA2STE/TB0.1/COM7/LCDS33)
RF_SPI_MISO: R35.2 U1.68(P7.1/UCA2SOMI/UCA2RXD/SMCLK/COM5/LCDS35)
RF_SPI_MOSI: R34.2 U1.67(P7.0/UCA2SIMO/UCA2TXD/ACLK/COM4/LCDS36)
RF_TXD: R29.2 U1.82(P8.3/UCA3SIMO/UCA3TXD/RTCCLK)
SOURCE_VCC: C10.1 C13.1 POW_SEL.2 R9.2 R19.2 R41.2 R43.2 R45.2 R47.2 U2.1(IN) U2.3(EN) U3.1(VIN) U3.12(EN)
USSXIN: C8.1 U1.97(USSXTIN) Y3.3(Out)
USSXOUT: R15.2 U1.98(USSXTOUT)
USSXT_BOUT: J7.1 U1.95(P8.7/UCB1STE/USSXT_BOUT/A13)
VCC_SENSE: R9.1 R10.2 U1.2(P2.3/TA0.0/UCA0STE/A15/C15)
VCC_SENSE_EN: R10.1 U1.1(P2.2/COUT/UCA0CLK/A14/C14)
VSET: R22.1 R49.2 U1.94(P8.6/UCB1SOMI/UCB1SCL/A12) U3.7(PG)
NetC7_1: C7.1 R15.1 Y3.1(In)
NetC11_2: C11.2 J8.1 R16.1
NetC12_2: C12.2 J8.7 R17.1
NetC15_1: C15.1 R26.1 Y1.2(OSC2)
NetJ5_5: J5.5 R28.1
NetJ5_7: J5.7 R29.1
NetJ5_9: J5.9 R27.1
NetJ5_13: J5.13 R33.2
NetJ5_15: J5.15 R38.2
NetJ5_17: J5.17 R50.2
NetJ5_19: J5.19 R51.2
NetJ6_4: J6.4 R37.2
NetJ6_6: J6.6 R32.1
NetJ6_12: J6.12 R34.1
NetJ6_14: J6.14 R35.1
NetJ6_16: J6.16 R36.2
NetJ6_18: J6.18 R31.1
NetJ6_20: J6.20 R30.1
NetL3_1: L3.1 U3.2(SW)
NetLED1_1: LED1.1(A) R23.2
NetLED2_1: LED2.1(A) R24.2
NetLED3_1: LED3.1(A) R25.2
NetR20_1: R20.1 R21.2 R22.2 U2.4(FB)
NetR41_1: R41.1 R42.1 U3.11(VSEL1)
NetR43_1: R43.1 R44.1 U3.10(VSEL2)
NetR45_1: R45.1 R46.1 U3.9(VSEL3)
NetR47_1: R47.1 R48.1 U3.8(VSEL4)

Not connected (* = marked no-connect by the designer): J5 2 3 6 8 10 11 12 14 16 18 20; J6 1 3 5 7 8 9 10 11 13 15 17 19; J34 6* 10* 13*; LCD 25(NC) 26(NC) 27(NC) 28(NC) 29(NC) 30(NC) 31(NC); U1 28(P2.4/TA0CLK/TB0CLK/TA1CLK/LCDS32) 92(P8.4/UCB1CLK/TA1.2/A10) 93(P8.5/UCB1SIMO/UCB1SDA/A11); U3 6(LOAD)

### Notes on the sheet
- Optional Vreg Circuit
- (near U3) TPS62740/2 can be used
- Vout  VSEL4  VSEL3  VSEL2  VSEL1
  1.8V      0           0           0          0
  1.9V      0           0           0          1
  2.0V      0           0           1          0
  2.1V      0           0           1          1
  2.2V      0           1           0          0
  2.3V      0           1           0          1
  2.4V      0           1           1          0
  2.5V      0           1           1          1
  2.6V      1           0           0          0
  2.7V      1           0           0          1
  2.8V      1           0           1          0
  2.9V      1           0           1          1
  3.0V      1           1           0          0
  3.1V      1           1           0          1
  3.2V      1           1           1          0
  3.3V      1           1           1          1
- (near R19) Optional Vreg circuit.
- TPS780/1/2 can be used
- Power
- Offsheet connection

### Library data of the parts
BUT_DOWN BUT_LEFT BUT_RIGHT BUT_SELECT BUT_UP = TL1015AF160QG: Switch, Tactile, SPST-NO, 0.05A, 12V, SMT; Manufacturer: E-Switch; SymbolCreator: a0412235; VDC_V: 12; SwitchFunction: Off-Mom; PositionCount: 1; CurrentRating_mA: 50
C1 C2 C5 C6 = GRM155R71C104KA88D: CAP, CERM, 0.1 µF, 16 V, +/- 10%, X7R, 0402; Manufacturer: MuRata; Value: 0.1uF; Polarized: N; CompType: Capacitor; U/M: EA; Cap_F: 0.0000001; Tolerance_%: 10; Value1: Unknown; VDC_V: 16; Value2: 16V; TaMin_C: -55; TaMax_C: 125; Cap_Case: 0402; AEC Category: Q200
C3 C4 C14 = GRM1555C1H102JA01D: CAP, CERM, 1000 pF, 50 V, +/- 5%, C0G/NP0, 0402; Manufacturer: MuRata; Value: 1000pF; Polarized: N; CompType: Capacitor; U/M: EA; Cap_F: 0.000000001; Tolerance_%: 5; Value1: Unknown; VDC_V: 50; Value2: 50V; TaMin_C: -55; TaMax_C: 125; Cap_Case: 0402; AEC Category: Q200
C7 C8 C15 C16 = GRM1555C1H120JA01D: CAP, CERM, 12 pF, 50 V, +/- 5%, C0G/NP0, 0402; Manufacturer: MuRata; Polarized: N; CompType: Capacitor; Value: 12pF; U/M: EA; Cap_F: 0.000000000012; Tolerance_%: 5; Value1: Unknown; VDC_V: 50; Value2: 50V; TaMin_C: -55; TaMax_C: 125; SizeArea_mm2: 0.5; SizeAreaWB_mm2: 3; SizeX_mm: 1; SizeZ_mm: 0.6; AEC Category: Q200
C9 = GRM21BR71C475KA73L: CAP, CERM, 4.7 µF, 16 V, +/- 10%, X7R, 0805; Manufacturer: MuRata; Value: 4.7uF; Polarized: N; CompType: Capacitor; U/M: EA; Cap_F: 0.0000047; Tolerance_%: 10; ESR_ohm: 0.006; Value1: 0.006 ohm; VDC_V: 16; Value2: 16V; TaMin_C: -55; TaMax_C: 125; Cap_Case: 0805; AEC Category: Q200
C10 C19 = GRM188R61A106ME69D: as C410 on sheet MCU018A_USB Hub and Pow
C11 C12 = GRM1885C1H102FA01J: CAP, CERM, 1000 pF, 50 V, +/- 1%, C0G/NP0, 0603; Manufacturer: MuRata; Value: 1000pF; Polarized: N; CompType: Capacitor; U/M: EA; Cap_F: 0.000000001; Value1: Unknown; VDC_V: 50; Value2: 50V; TaMin_C: -55; TaMax_C: 125; Cap_Case: 0603; AEC Category: Q200
C13 C20 = GRM155R71C104KA88D: as C400 on sheet MCU018A_USB Hub and Pow
C17 C18 = GRM1555C1H120JA01D: CAP, CERM, 12 pF, 50 V, +/- 5%, C0G/NP0, 0402; Manufacturer: MuRata; Value: 12pF; Polarized: N; CompType: Capacitor; U/M: EA; Cap_F: 0.000000000012; Tolerance_%: 5; Value1: Unknown; VDC_V: 50; Value2: 50V; TaMin_C: -55; TaMax_C: 125; Cap_Case: 0402; AEC Category: Q200
C21 = GRM21BR60J476ME15L: CAP, CERM, 47 µF, 6.3 V, +/- 20%, X5R, 0805; Manufacturer: MuRata; Polarized: N; CompType: Capacitor; Value: 47uF; U/M: EA; Cap_F: 0.000047; Tolerance_%: 20; Value1: Unknown; VDC_V: 6.3; Value2: 6.3V; TaMin_C: -55; TaMax_C: 85; Cap_Case: 0805; SizeArea_mm2: 2.5; SizeAreaWB_mm2: 6.75; SizeX_mm: 2; SizeY_mm: 1.25; SizeZ_mm: 1.45; AEC Category: Q200
C22 = GRM188R71A105KA61D: CAP, CERM, 1 µF, 10 V, +/- 10%, X7R, 0603; Manufacturer: MuRata; Polarized: N; CompType: Capacitor; Value: 1uF; U/M: EA; Cap_F: 0.000001; Tolerance_%: 10; ESR_ohm: 0.011; Value1: 0.011 ohm; Value2: 10V; TaMin_C: -55; TaMax_C: 125; Cap_Case: 0603; AEC Category: Q200; SizeArea_mm2: 1.28; SizeAreaWB_mm2: 4.68; SizeX_mm: 1.6; SizeY_mm: 0.8; SizeZ_mm: 1
C23 C24 = GRM21BR60J476ME15L: CAP, CERM, 47 µF, 6.3 V, +/- 20%, X5R, 0805; Manufacturer: MuRata; Polarized: N; CompType: Capacitor; Value: 47uF; U/M: EA; Cap_F: 0.000047; Tolerance_%: 20; Value1: Unknown; VDC_V: 6.3; Value2: 6.3V; TaMin_C: -55; TaMax_C: 85; Cap_Case: 0805; AEC Category: Q200; SizeArea_mm2: 2.5; SizeAreaWB_mm2: 6.75; SizeX_mm: 2; SizeY_mm: 1.25; SizeZ_mm: 1.45
C25-C27 = GRM188R71A105KA61D: CAP, CERM, 1 µF, 10 V, +/- 10%, X7R, 0603; Manufacturer: MuRata; Polarized: N; CompType: Capacitor; Value: 1uF; U/M: EA; Cap_F: 0.000001; Tolerance_%: 10; ESR_ohm: 0.011; Value1: 0.011 ohm; Value2: 10V; TaMin_C: -55; TaMax_C: 125; Cap_Case: 0603; SizeArea_mm2: 1.28; SizeAreaWB_mm2: 4.68; SizeX_mm: 1.6; SizeY_mm: 0.8; SizeZ_mm: 1; AEC Category: Q200
C28 = GRM155R71C104KA88D: CAP, CERM, 0.1 µF, 16 V, +/- 10%, X7R, 0402; Manufacturer: MuRata; Polarized: N; CompType: Capacitor; Value: 0.1uF; U/M: EA; Cap_F: 0.0000001; Tolerance_%: 10; Value1: Unknown; VDC_V: 16; Value2: 16V; TaMin_C: -55; TaMax_C: 125; SizeArea_mm2: 0.5; SizeAreaWB_mm2: 3; SizeX_mm: 1; SizeZ_mm: 0.6; AEC Category: Q200
J4 J7 = HMTSW-102-07-G-S-240: Header, 100mil, 2x1, Gold, TH; Manufacturer: Samtec; SymbolCreator: a0412235
J5 J6 = TSW-110-07-G-D: Header, 100mil, 10x2, Gold, TH; Manufacturer: Samtec; SymbolCreator: a0412235; Pitch_mm: 2.54; Gender: Male; Shrouded: N; Row_Count: 2; Current_A: 6.3; Voltage_V: 550; Cert_CSA: Y
J8 = TSW-104-07-G-D: Header, 100mil, 4x2, Gold, TH; Manufacturer: Samtec; SymbolCreator: a0411947; Pitch_mm: 2.54; Gender: Male; Shrouded: N; Row_Count: 2; Current_A: 6.3; Voltage_V: 550; Cert_CSA: Y
J30 = TSW-102-07-G-D: Header, 100mil, 2x2, Gold, TH; Manufacturer: Samtec; SymbolCreator: a0412235; Pitch_mm: 2.54; Gender: Male; Shrouded: N; Row_Count: 2; Current_A: 6.3; Voltage_V: 550; Cert_CSA: Y
J31-J33 = TSW-102-07-G-S: Header, 100mil, 2x1, Gold, TH; Manufacturer: Samtec; SymbolCreator: a0412235; Pitch_mm: 2.54; Gender: Male; Shrouded: N; Row_Count: 1; Current_A: 6.3; Voltage_V: 550; Cert_CSA: Y
J34 = SBH11-PBPC-D07-ST-BK: Header (shrouded), 100 mil, 7x2, Gold, TH; Manufacturer: Sullins Connector Solutions; SymbolCreator: a0412235
L1 L2 = MPZ2012S601A: Ferrite Bead, 600 ohm @ 100 MHz, 2 A, 0805; Manufacturer: TDK; Alternate PartNumber: MPZ2012S601AT000; Imax_A: 2; DCR_ohm: 0.1; Value1: 0.1 ohm; Value2: 2A; ZTyp@100MHz_Ohm: 600
L3 = VLF302515MT-2R2M: Inductor, Shielded, Ferrite, 2.2 µH, 1.57 A, 0.042 ohm, SMD; Manufacturer: TDK; Value: 2.2uH; Ind_H: 2.2E-6; Imax_A: 1.57; Irms: 2.71A @ 40C rise; Isat: 1.57A @ 30% inductance drop; DCR_ohm: 0.042; Value2: 1.57A; AEC Category: Q200
LCD = FH-1138P: 108 Segment LCD Display, TH; Manufacturer: Adkom Elektronik; SymbolCreator: Altium; SizeAreaWB_mm2: 1571.8; SizeArea_mm2: 1405.6; SizeX_mm: 25.1; SizeY_mm: 56; SizeZ_mm: 3.1
LED1 LED2 = LTST-C191TGKT: as D201 on sheet MCU018A_Comm Interface
LED3 = LTST-C190CKT: as D203 on sheet MCU018A_Comm Interface
MCU_RESET = B3U-1000P: as S201 on sheet MCU018A_Comm Interface
NT1-NT3 = Net-Tie: Single point connection between nets.; SymbolCreator: codlsc
POW_SEL = SS-13D16-VG 4 PA: Switch, Slide, SP3T, On-On-On, 3 Pos, 0.3A, 30 VDC, TH; Manufacturer: C&K Components; SymbolCreator: Altium; VDC_V: 30; PositionCount: 3; CurrentRating_mA: 300
R9 R10 = CRCW0402100KJNED: RES, 100 k, 5%, 0.063 W, 0402; Manufacturer: Vishay-Dale; Value: 100k; CompType: Resistor; Res_ohm: 100000; Tolerance_%: 5; Power_W: 0.063; Value2: 0.063W; VDC_V: 50; TempCo: 200 ppm/C; EIA_Code: E24; U/M: EA
R11 = 3224W-1-204E: Trimmer, 200 K, 0.25 W, SMD; Manufacturer: Bourns; Sim Note: Enter the Resistance value and the set point into parameter fields.; SymbolCreator: a0412235
R12-R14 = CRCW0402330KJNED: RES, 330 k, 5%, 0.063 W, 0402; Manufacturer: Vishay-Dale; Value: 330k; CompType: Resistor; Res_ohm: 330000; Tolerance_%: 5; Power_W: 0.063; Value2: 0.063W; VDC_V: 50; TempCo: 200 ppm/C; EIA_Code: E24; U/M: EA; AEC Category: Q200
R15 R26 = CRCW040222R0JNED: RES, 22, 5%, 0.063 W, 0402; Manufacturer: Vishay-Dale; Value: 22; CompType: Resistor; Value_Code: 22R0; Tolerance_%: 5; Power_W: 0.063; Value2: 0.063W; VDC_V: 50; TempCo: 200 ppm/C; EIA_Code: E24; U/M: EA; AEC Category: Q200
R16 R17 = CRCW0402200RFKED: RES, 200, 1%, 0.063 W, 0402; Manufacturer: Vishay-Dale; Value: 200; CompType: Resistor; Value_Code: 200R; Tolerance_%: 1; Power_W: 0.063; Value2: 0.063W; VDC_V: 50; TempCo: 100 ppm/C; EIA_Code: E96; U/M: EA; AEC Category: Q200
R18 = CRCW040247K0JNED: RES, 47 k, 5%, 0.063 W, 0402; Manufacturer: Vishay-Dale; Value: 47k; CompType: Resistor; Res_ohm: 47000; Value_Code: 47k0; Tolerance_%: 5; Power_W: 0.063; Value2: 0.063W; VDC_V: 50; TempCo: 200 ppm/C; EIA_Code: E24; U/M: EA
R19 = CRCW08050000Z0EA: RES, 0, 5%, 0.125 W, 0805; Manufacturer: Vishay-Dale; Value: 0; CompType: Resistor; Value_Code: 0000; Tolerance_%: 5; Power_W: 0.125; Value2: 0.125W; VDC_V: 150; TempCo: 200 ppm/C; EIA_Code: E24; U/M: EA; AEC Category: Q200
R20-R22 R41-R49 = Resistor: RES, xxx ohm, x%, xW, [PackageReference]; U/M: EA
R23 R24 = CRCW0402390RJNED: RES, 390, 5%, 0.063 W, 0402; Manufacturer: Vishay-Dale; Value: 390; CompType: Resistor; Value_Code: 390R; Tolerance_%: 5; Power_W: 0.063; Value2: 0.063W; VDC_V: 50; TempCo: 200 ppm/C; EIA_Code: E24; U/M: EA; AEC Category: Q200
R25 = CRCW0402470RJNED: RES, 470, 5%, 0.063 W, 0402; Manufacturer: Vishay-Dale; Value: 470; CompType: Resistor; Value_Code: 470R; Tolerance_%: 5; Power_W: 0.063; Value2: 0.063W; VDC_V: 50; TempCo: 200 ppm/C; EIA_Code: E24; U/M: EA; AEC Category: Q200
R27-R38 = CRCW04020000Z0ED: RES, 0, 5%, 0.063 W, 0402; Manufacturer: Vishay-Dale; Value: 0; CompType: Resistor; Value_Code: 0000; Tolerance_%: 5; Power_W: 0.063; Value2: 0.063W; VDC_V: 50; TempCo: 200 ppm/C; EIA_Code: E24; U/M: EA
R50 R51 = CRCW04020000Z0ED: RES, 0, 5%, 0.063 W, 0402; Manufacturer: Vishay-Dale; CompType: Resistor; Value: 0; Value_Code: 0000; Tolerance_%: 5; Power_W: 0.063; Value2: 0.063W; VDC_V: 50; TempCo: 200 ppm/C; SizeArea_mm2: 0.5; SizeX_mm: 1; SizeZ_mm: 0.6; EIA_Code: E24; U/M: EA; AEC Category: Q200
U1 = MSP430FR6047IPZR: Mixed-Signal Microcontroller, PZ0100A (LQFP-100); Manufacturer: Texas Instruments; SymbolCreator: Altium; SizeArea_mm2: 256; SizeAreaWB_mm2: 324; SizeX_mm: 16; SizeZ_mm: 1.6; CompType: IC; U/M: EA
U2 = TPS78001DDCR: Single Output LDO, 150 mA, Adjustable 1.22 to 5.25 V Output, 2.2 to 5.5 V Input, with 500 nA Quiescent Current, 5-pin SOT (DDC), -40 to 125 degC, Green (RoHS & no Sb/Br); Manufacturer: Texas Instruments; Alternate PartNumber: Equivalent; Accuracy(%): 3; Dynamic Voltage Scaling: TRUE; Iout(Max)(A): 0.15; Iq(Typ)(mA): 0.0005; SubFamily: Single Channel LDO; Vdo(Typ)(mV): 200; Vin(Max)(V): 5.5; Vin(Min)(V): 2.2; Vout Adj(Max)(V): 5.25; Vout Adj(Min)(V): 1.22
U3 = TPS62740DSSR: 360nA IQ Step Down Converter for Low Power Applications, DSS0012A; Alternate PartNumber: TPS62740DSST; Manufacturer: Texas Instruments; SymbolCreator: Altium; SizeArea_mm2: 6; SizeAreaWB_mm2: 12; SizeX_mm: 3; SizeY_mm: 2; SizeZ_mm: 0.8; CompType: IC; U/M: EA
Y1 = ABM3-8.000MHZ-D2Y-T: Crystal, 8MHz, SMD; Manufacturer: Abracon Corporation; SymbolCreator: a0412235; U/M: EA; TaMin_C: -40; TaMax_C: 85; Frequency Stability: ±30ppm
Y2 = ABS07-32.768KHZ-9-T: CRYSTAL, 32.768KHZ, 9PF, SMD; Manufacturer: Abracon Corporation; SymbolCreator: a0412235; U/M: EA; TaMin_C: -40; TaMax_C: 85; Frequency Stability: ±20ppm
Y3 = AWSCR-8.00CV-T: Ceramic Resonator, 8MHz, 22pF, SMD; Manufacturer: Abracon Corporation; SymbolCreator: a0799721; SizeAreaWB_mm2: 19.27; SizeArea_mm2: 11.47; SizeX_mm: 3.7; SizeY_mm: 3.1; SizeZ_mm: 1.2; U/M: EA; TaMin_C: -25; TaMax_C: 85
